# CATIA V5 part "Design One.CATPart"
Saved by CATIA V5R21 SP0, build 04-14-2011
Part number: Design One
Bounding box of the stored display mesh (mm): x -90 to 271.101, y -84.571 to 109.466, z 0 to 0
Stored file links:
  C:\Users\RIAD MAHAMUD PIASH\Desktop\Design One.CATPart
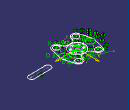
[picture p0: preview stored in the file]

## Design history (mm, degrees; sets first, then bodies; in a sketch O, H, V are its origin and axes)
Body1 (main body)
  Sketch1 on xy-plane, origin (0, 0, 0), H (1, 0, 0), V (0, 1, 0)
    circle A1 centre (70, 0) radius 20
    point P1 (70, 0)
    line L1 (89.3486, -5.0627) -> (73.5831, -65.3158)
    point P2 (73.5831, -65.3158)
    arc A2 centre (53.2671, -60) radius 21 from (73.5831, -65.3158) to (33.1455, -66.0103) cw
    point P3 (53.2671, -60)
    point P4 (32.3581, -61.9536)
    line L2 (28.49, -54.5476) -> (26.5722, -50.8758)
    point P5 (26.5722, -50.8758)
    arc A3 centre (8.8446, -60.1349) radius 20 from (26.5722, -50.8758) to (9.1445, -40.1372) ccw
    point P7 (9.1445, -40.1372)
    line L3 (9.1445, -40.1372) -> (0, -40)
    point P8 (0, -40)
    point P9 (89.3486, -5.0627)
    circle A4 centre (53.2671, -60) radius 15
    point P11 (-73.5831, -65.3158)
    point P13 (-89.3486, -5.0627)
    circle A5 centre (-70, 0) radius 20
    line L4 (-89.3486, -5.0627) -> (-73.5831, -65.3158)
    point P14 (-32.3581, -61.9536)
    arc A6 centre (-53.2671, -60) radius 21 from (-73.5831, -65.3158) to (-32.8822, -65.0454) ccw
    circle A7 centre (-53.2671, -60) radius 15
    point P15 (-26.5722, -50.8758)
    point P17 (-9.1445, -40.1372)
    point P18 (0, -40)
    line L5 (-30.0065, -57.4512) -> (-26.5722, -50.8758)
    arc A8 centre (-8.8446, -60.1349) radius 20 from (-26.5722, -50.8758) to (-9.1445, -40.1372) cw
    line L6 (-9.1445, -40.1372) -> (0, -40)
    point P19 (73.5831, 65.3158)
    point P21 (32.3581, 61.9536)
    point P22 (26.5722, 50.8758)
    point P24 (9.1445, 40.1372)
    point P25 (0, 40)
    point P26 (-73.5831, 65.3158)
    point P28 (-32.3581, 61.9536)
    point P29 (-26.5722, 50.8758)
    point P31 (-9.1445, 40.1372)
    point P32 (0, 40)
    arc A9 centre (53.2671, 60) radius 21 from (73.5831, 65.3158) to (33.4464, 66.9385) ccw
    line L7 (26.0511, 49.8781) -> (26.5722, 50.8758)
    arc A10 centre (8.8446, 60.1349) radius 20 from (26.5722, 50.8758) to (9.1445, 40.1372) cw
    line L8 (9.1445, 40.1372) -> (0, 40)
    circle A11 centre (53.2671, 60) radius 15
    arc A12 centre (-53.2671, 60) radius 21 from (-73.5831, 65.3158) to (-33.2191, 66.2514) cw
    circle A13 centre (-53.2671, 60) radius 15
    line L9 (-27.9809, 53.573) -> (-26.5722, 50.8758)
    arc A14 centre (-8.8446, 60.1349) radius 20 from (-26.5722, 50.8758) to (-9.1445, 40.1372) ccw
    line L10 (-9.1445, 40.1372) -> (0, 40)
    point P33 (-89.3486, 5.0627)
    line L11 (-89.3486, 5.0627) -> (-73.5831, 65.3158)
    point P34 (89.3486, 5.0627)
    line L12 (89.3486, 5.0627) -> (73.5831, 65.3158)
    circle A15 centre (0, 0) radius 39.9955
    point P35 (0, 39.9955)
    arc A16 centre (0, 0) radius 32 from (-29.0908, 13.3315) to (-29.0908, -13.3315) ccw
    arc A17 centre (0, 0) radius 21.6063 from (-20.0304, 8.1004) to (-20.0304, -8.1004) ccw
    circle A18 centre (0, 0) radius 16
    arc A19 centre (-28.9943, -84.5714) radius 64.8527 from (33.1455, -66.0103) to (28.49, -54.5476) ccw
    arc A20 centre (0.2203, -73.2385) radius 34.1014 from (-32.8822, -65.0454) to (-30.0065, -57.4512) cw
    arc A21 centre (40.0177, 89.0884) radius 76.7148 from (-33.2191, 66.2514) to (-27.9809, 53.573) ccw
    arc A22 centre (-88.0374, 109.466) radius 128.7125 from (33.4464, 66.9385) to (26.0511, 49.8781) cw
    construction line L13 (-54.579, 34.9753) -> (-3.4743, 5.47)
    construction line L14 (-57.579, 29.7791) -> (-6.4743, 0.2739)
    construction line L15 (-57.579, -29.7791) -> (-6.4743, -0.2739)
    construction line L16 (-54.579, -34.9753) -> (-3.4743, -5.47)
    construction line L17 (-3, -64.7544) -> (-3, -5.7439)
    construction line L18 (3, -64.7544) -> (3, -5.7439)
    construction line L19 (54.579, -34.9753) -> (3.4743, -5.47)
    construction line L20 (57.579, -29.7791) -> (6.4743, -0.2739)
    construction line L21 (57.579, 29.7791) -> (6.4743, 0.2739)
    construction line L22 (54.579, 34.9753) -> (3.4743, 5.47)
    construction line L23 (3, 64.7544) -> (3, 5.7439)
    construction line L24 (-3, 64.7544) -> (-3, 5.7439)
    point P72 (-26.0908, 18.5276)
    point P73 (-29.0908, 13.3315)
    point P74 (-17.0304, 13.2966)
    point P75 (-20.0304, 8.1004)
    arc A23 centre (0, 0) radius 32 from (-3, 31.8591) to (-26.0908, 18.5276) ccw
    point P77 (-3, 31.8591)
    arc A24 centre (0, 0) radius 21.6063 from (-3, 21.397) to (-17.0304, 13.2966) ccw
    point P80 (20.0304, 8.1004)
    arc A25 centre (0, 0) radius 21.6063 from (17.0304, 13.2966) to (3, 21.397) ccw
    point P81 (17.0304, 13.2966)
    point P82 (29.0908, 13.3315)
    arc A26 centre (0, 0) radius 32 from (26.0908, 18.5276) to (3, 31.8591) ccw
    point P83 (26.0908, 18.5276)
    point P84 (26.0908, -18.5276)
    arc A27 centre (0, 0) radius 32 from (29.0908, -13.3315) to (29.0908, 13.3315) ccw
    point P85 (29.0908, -13.3315)
    point P86 (17.0304, -13.2966)
    arc A28 centre (0, 0) radius 21.6063 from (20.0304, -8.1004) to (20.0304, 8.1004) ccw
    point P87 (20.0304, -8.1004)
    point P88 (-3, -31.8591)
    arc A29 centre (0, 0) radius 32 from (3, -31.8591) to (26.0908, -18.5276) ccw
    point P89 (3, -31.8591)
    point P90 (-3, -21.397)
    arc A30 centre (0, 0) radius 21.6063 from (3, -21.397) to (17.0304, -13.2966) ccw
    point P91 (3, -21.397)
    point P92 (-29.0908, -13.3315)
    arc A31 centre (0, 0) radius 32 from (-26.0908, -18.5276) to (-3, -31.8591) ccw
    point P93 (-26.0908, -18.5276)
    point P94 (-20.0304, -8.1004)
    arc A32 centre (0, 0) radius 21.6063 from (-17.0304, -13.2966) to (-3, -21.397) ccw
    point P95 (-17.0304, -13.2966)
    line L25 (-29.0908, 13.3315) -> (-20.0304, 8.1004)
    line L26 (-26.0908, 18.5276) -> (-17.0304, 13.2966)
    line L27 (-26.0908, -18.5276) -> (-17.0304, -13.2966)
    line L28 (-29.0908, -13.3315) -> (-20.0304, -8.1004)
    line L29 (3, -31.8591) -> (3, -21.397)
    line L30 (-3, -31.8591) -> (-3, -21.397)
    line L31 (29.0908, -13.3315) -> (20.0304, -8.1004)
    line L32 (26.0908, -18.5276) -> (17.0304, -13.2966)
    line L33 (26.0908, 18.5276) -> (17.0304, 13.2966)
    line L34 (29.0908, 13.3315) -> (20.0304, 8.1004)
    line L35 (-3, 31.8591) -> (-3, 21.397)
    line L36 (3, 31.8591) -> (3, 21.397)
    line L37 (-29.0908, 13.3315) -> (-20.0304, 8.1004)
    line L38 (-26.0908, 18.5276) -> (-17.0304, 13.2966)
    construction line L39 (166.3706, 8.5654) -> (256.1016, 9.9113)
    line L40 (166.1456, 23.5637) -> (255.8766, 24.9096)
    line L41 (256.3265, -5.087) -> (166.5956, -6.4329)
    arc A33 centre (256.1016, 9.9113) radius 15 from (255.8766, 24.9096) to (256.3265, -5.087) cw
    arc A34 centre (166.3706, 8.5654) radius 15 from (166.5956, -6.4329) to (166.1456, 23.5637) cw
    point P126 (261.101, 9.9863)
    radius A1 = 20
    distance P1 V = 70
    distance H P3 = 60
    radius A2 = 21
    radius A3 = 20
    distance P8 H = 40
    radius A4 = 15
    radius A19 = 64.8527
    radius A20 = 34.1014
    radius A21 = 76.7148
    radius A22 = 128.7125
    radius A16 = 32
    radius A17 = 21.6063
    radius A18 = 16
    distance L39 L40 = 15
    coincidence: P1 H, L2 O, P8 V, A1 P9, A15 P35, P35 V, A2 P4, L2 P4, A6 P14, L5 P14, A12 P28, L9 P28, A9 P21, L7 P21, L13 P72, L14 P73, L13 P74, L14 P75, L24 P77, A16 A23, A17 A24, L21 P80, L22 P81, A17 A25, L21 P82, L22 P83, A16 A26, L19 P84, L20 P85, A16 A27, L19 P86, L20 P87, A17 A28, L17 P88, L18 P89, A16 A29, L17 P90, L18 P91, A17 A30, L15 P92, L16 P93, A16 A31, L15 P94, L16 P95, A17 A32, P126 L39
    tangency: A2 L1, A3 L2, L3 A3, L1 A1, A15 L10, A19 A2, A19 L2, A20 A6, A20 L5, A21 A12, A21 L9, A22 A9, A22 L7, A33 L40, A34 L40, A33 L41, A34 L41
    symmetry: P2 P11 V, P9 P13 V, A1 A5 V, L1 L4 V, P4 P14 V, A2 A6 V, A4 A7 V, P5 P15 V, P7 P17 V, P8 P18 V, L2 L5 V, A3 A8 V, L3 L6 V, P2 P19 H, P4 P21 H, P5 P22 H, P7 P24 H, P8 P25 H, P11 P26 H, P14 P28 H, P15 P29 H, P17 P31 H, P18 P32 H, A2 A9 H, L2 L7 H, A3 A10 H, L3 L8 H, A4 A11 H, A6 A12 H, A7 A13 H, L5 L9 H, A8 A14 H, L6 L10 H, P13 P33 H, L4 L11 H, P9 P34 H, L1 L12 H
    parallelism: L26 L25, L39 L8
  Plane1: type Offset, RefPlane xy-plane, Offset 100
